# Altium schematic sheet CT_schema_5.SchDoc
size 367 x 335 mm
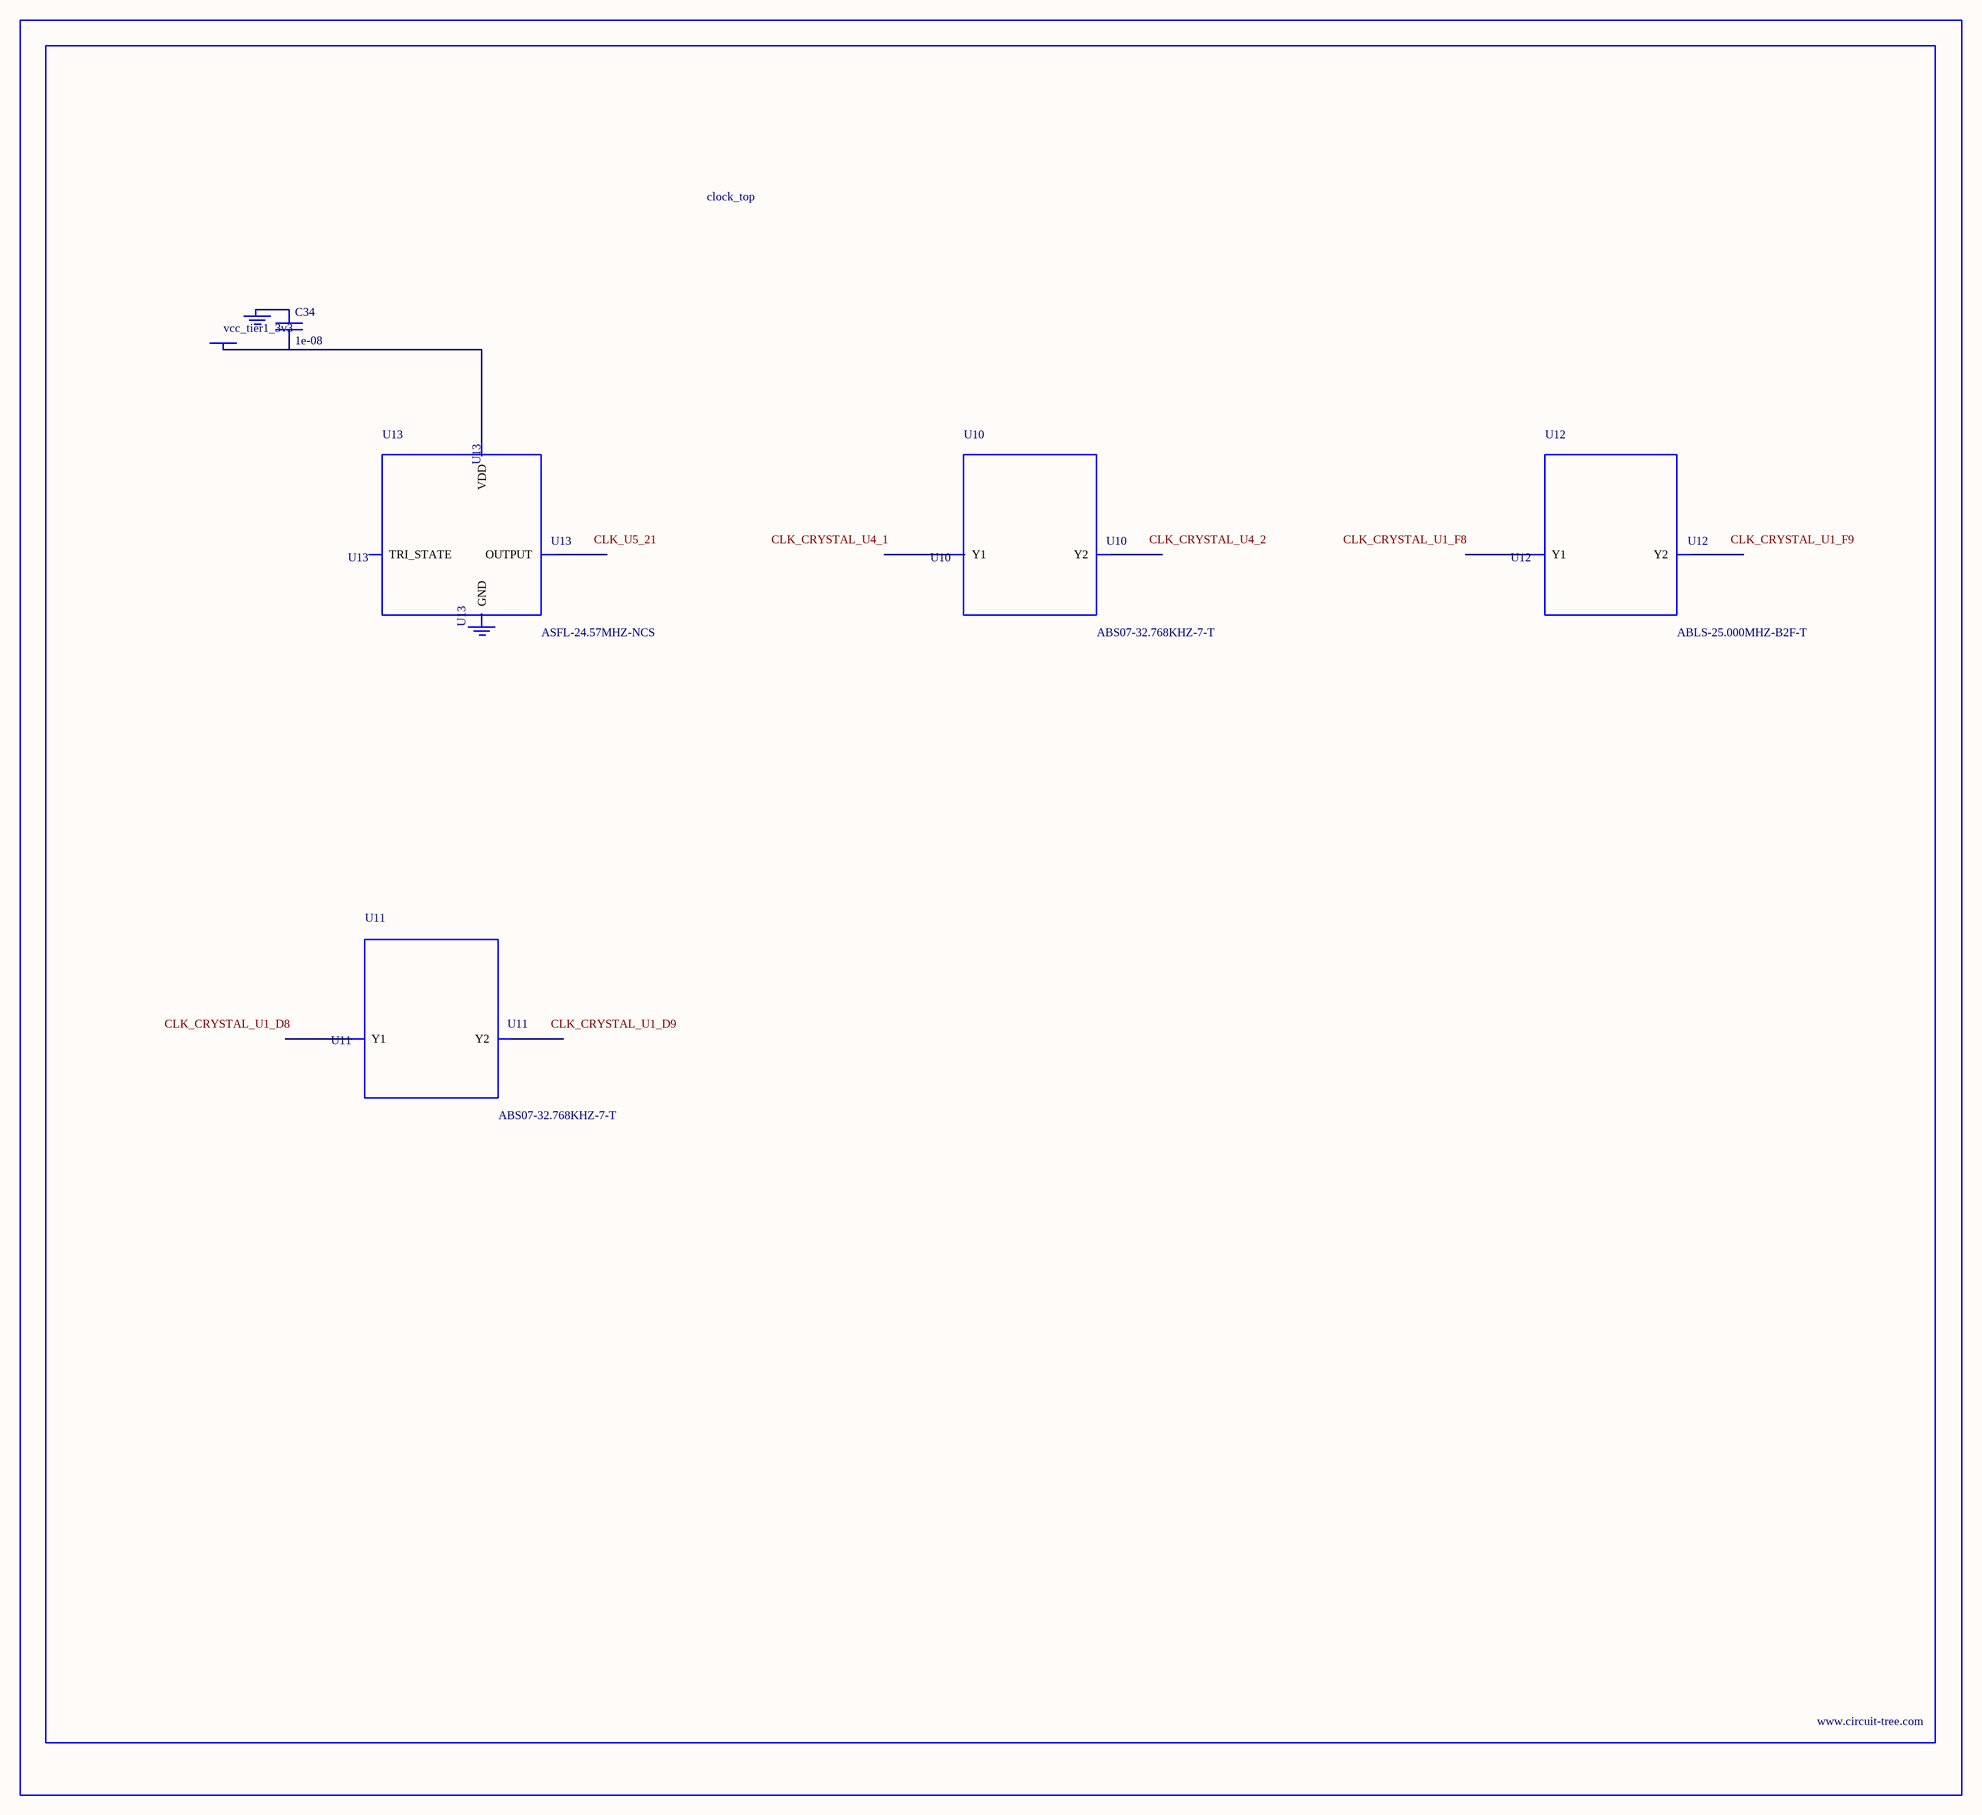
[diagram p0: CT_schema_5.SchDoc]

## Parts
BORDER4  (no value)
C34  1e-08  [C0402]
GND_INSTANCE_4_0  (no value)
GND_INSTANCE_4_1  (no value)
POWER_INSTANCE_4_0  vcc_tier1_3v3
U10  ABS07-32.768KHZ-7-T  [ABS07-32.768KHZ-7-T]
U11  ABS07-32.768KHZ-7-T  [ABS07-32.768KHZ-7-T]
U12  ABLS-25.000MHZ-B2F-T  [ABLS-25.000MHZ-B2F-T]
U13  ASFL-24.57MHZ-NCS  [ASFL1]

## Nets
NetC34_1: C34.1 GND_INSTANCE_4_0.0(GND)
NetC34_2: C34.2 POWER_INSTANCE_4_0.0(PWR) U13.4(VDD)

Not connected (* = marked no-connect by the designer): GND_INSTANCE_4_1 0(GND); U10 1(Y1) 2(Y2); U11 1(Y1) 2(Y2); U12 1(Y1) 2(Y2); U13 1(TRI_STATE) 2(GND) 3(OUTPUT)

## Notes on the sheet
- Labels drawn without touching a wire or pin: CLK_CRYSTAL_U1_D8, CLK_CRYSTAL_U1_D9, CLK_CRYSTAL_U1_F8, CLK_CRYSTAL_U1_F9, CLK_CRYSTAL_U4_1, CLK_CRYSTAL_U4_2, CLK_U5_21

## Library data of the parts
BORDER4 = BORDER_PAGE4
C34 = C0402C103K3RAC
GND_INSTANCE_4_0 GND_INSTANCE_4_1 = GND
POWER_INSTANCE_4_0 = PWR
